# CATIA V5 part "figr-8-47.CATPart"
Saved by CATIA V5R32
Part number: Part1
Bounding box of the stored display mesh (mm): x -46.99 to 46.99, y -111.421 to 111.421, z 0 to 30
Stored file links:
  D:\PROJECTS\Project 2022\CATIA V5 6R 2022\Resources\Part Files\c08_catia_v5_6r2022_prt\figr-8-47.CATPart
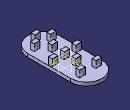
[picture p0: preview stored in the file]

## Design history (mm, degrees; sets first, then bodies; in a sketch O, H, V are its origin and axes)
Body1 (main body)
  Sketch1 on xy-plane, origin (0, 0, 0), H (1, 0, 0), V (0, 1, 0)
    construction line L1 (-46.9897, 64.4313) -> (46.9897, 64.4313)
    line L2 (46.9897, 64.4313) -> (46.9897, -64.4313)
    construction line L3 (46.9897, -64.4313) -> (-46.9897, -64.4313)
    line L4 (-46.9897, -64.4313) -> (-46.9897, 64.4313)
    axis line L5 (46.9897, -64.4313) -> (-46.9897, 64.4313)
    arc A1 centre (0, 64.4313) radius 46.9897 from (-46.9897, 64.4313) to (46.9897, 64.4313) cw
    arc A2 centre (0, -64.4313) radius 46.9897 from (-46.9897, -64.4313) to (46.9897, -64.4313) ccw
    point P7 (0, -111.4211)
    length L3 = 93.9795
    length L2 = 128.8627
    horizontal: L1 H, L3 H
    vertical: L2 V, L4 V
    midpoint: O L5
    tangency: A1 L2, A2 L4
    coincidence: A2 P7, P7 V
  Pad1: profile Sketch1, direction (0, 0, 1), length 10
  Sketch2 on face of Pad1, origin (0, 0, 10), H (1, 0, 0), V (0, 1, 0)
    line L1 (-8.4317, -82.0722) -> (8.3047, -82.0722)
    line L2 (8.3047, -82.0722) -> (8.3047, -93.8638)
    line L3 (8.3047, -93.8638) -> (-8.4317, -93.8638)
    line L4 (-8.4317, -93.8638) -> (-8.4317, -82.0722)
    horizontal: L1 H, L3 H
    vertical: L2 V, L4 V
  Pad2: profile Sketch2, direction (0, 0, 1), length 20
  Sketch3 on face of Pad1, origin (0, 0, 10), H (1, 0, 0), V (0, 1, 0)
    point P1 (-25.1683, -66.0965)
    point P2 (23.8999, -66.0965)
    point P3 (-35.058, 0)
    point P4 (35.3111, 0)
    point P5 (-25.1683, 70.4575)
    point P6 (23.8999, 70.4575)
    point P7 (0, 0)
    point P8 (0, -36.8078)
    point P9 (0, 34.322)
    coincidence: P3 H, P4 H, P7 O, P8 V, P9 V
  UserPattern1: of Pad2, copies 10, at the points of Sketch3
